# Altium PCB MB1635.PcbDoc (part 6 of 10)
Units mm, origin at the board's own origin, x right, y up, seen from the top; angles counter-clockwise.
Board outline 127 x 97 mm, 6 copper layers (Top Layer, Signal Layer 1, Signal Layer 2, Signal Layer 3, Signal Layer 4, Bottom Layer), stack 1.557 mm thick; 593 components, 478 nets, 2435 pads, 1743 vias.
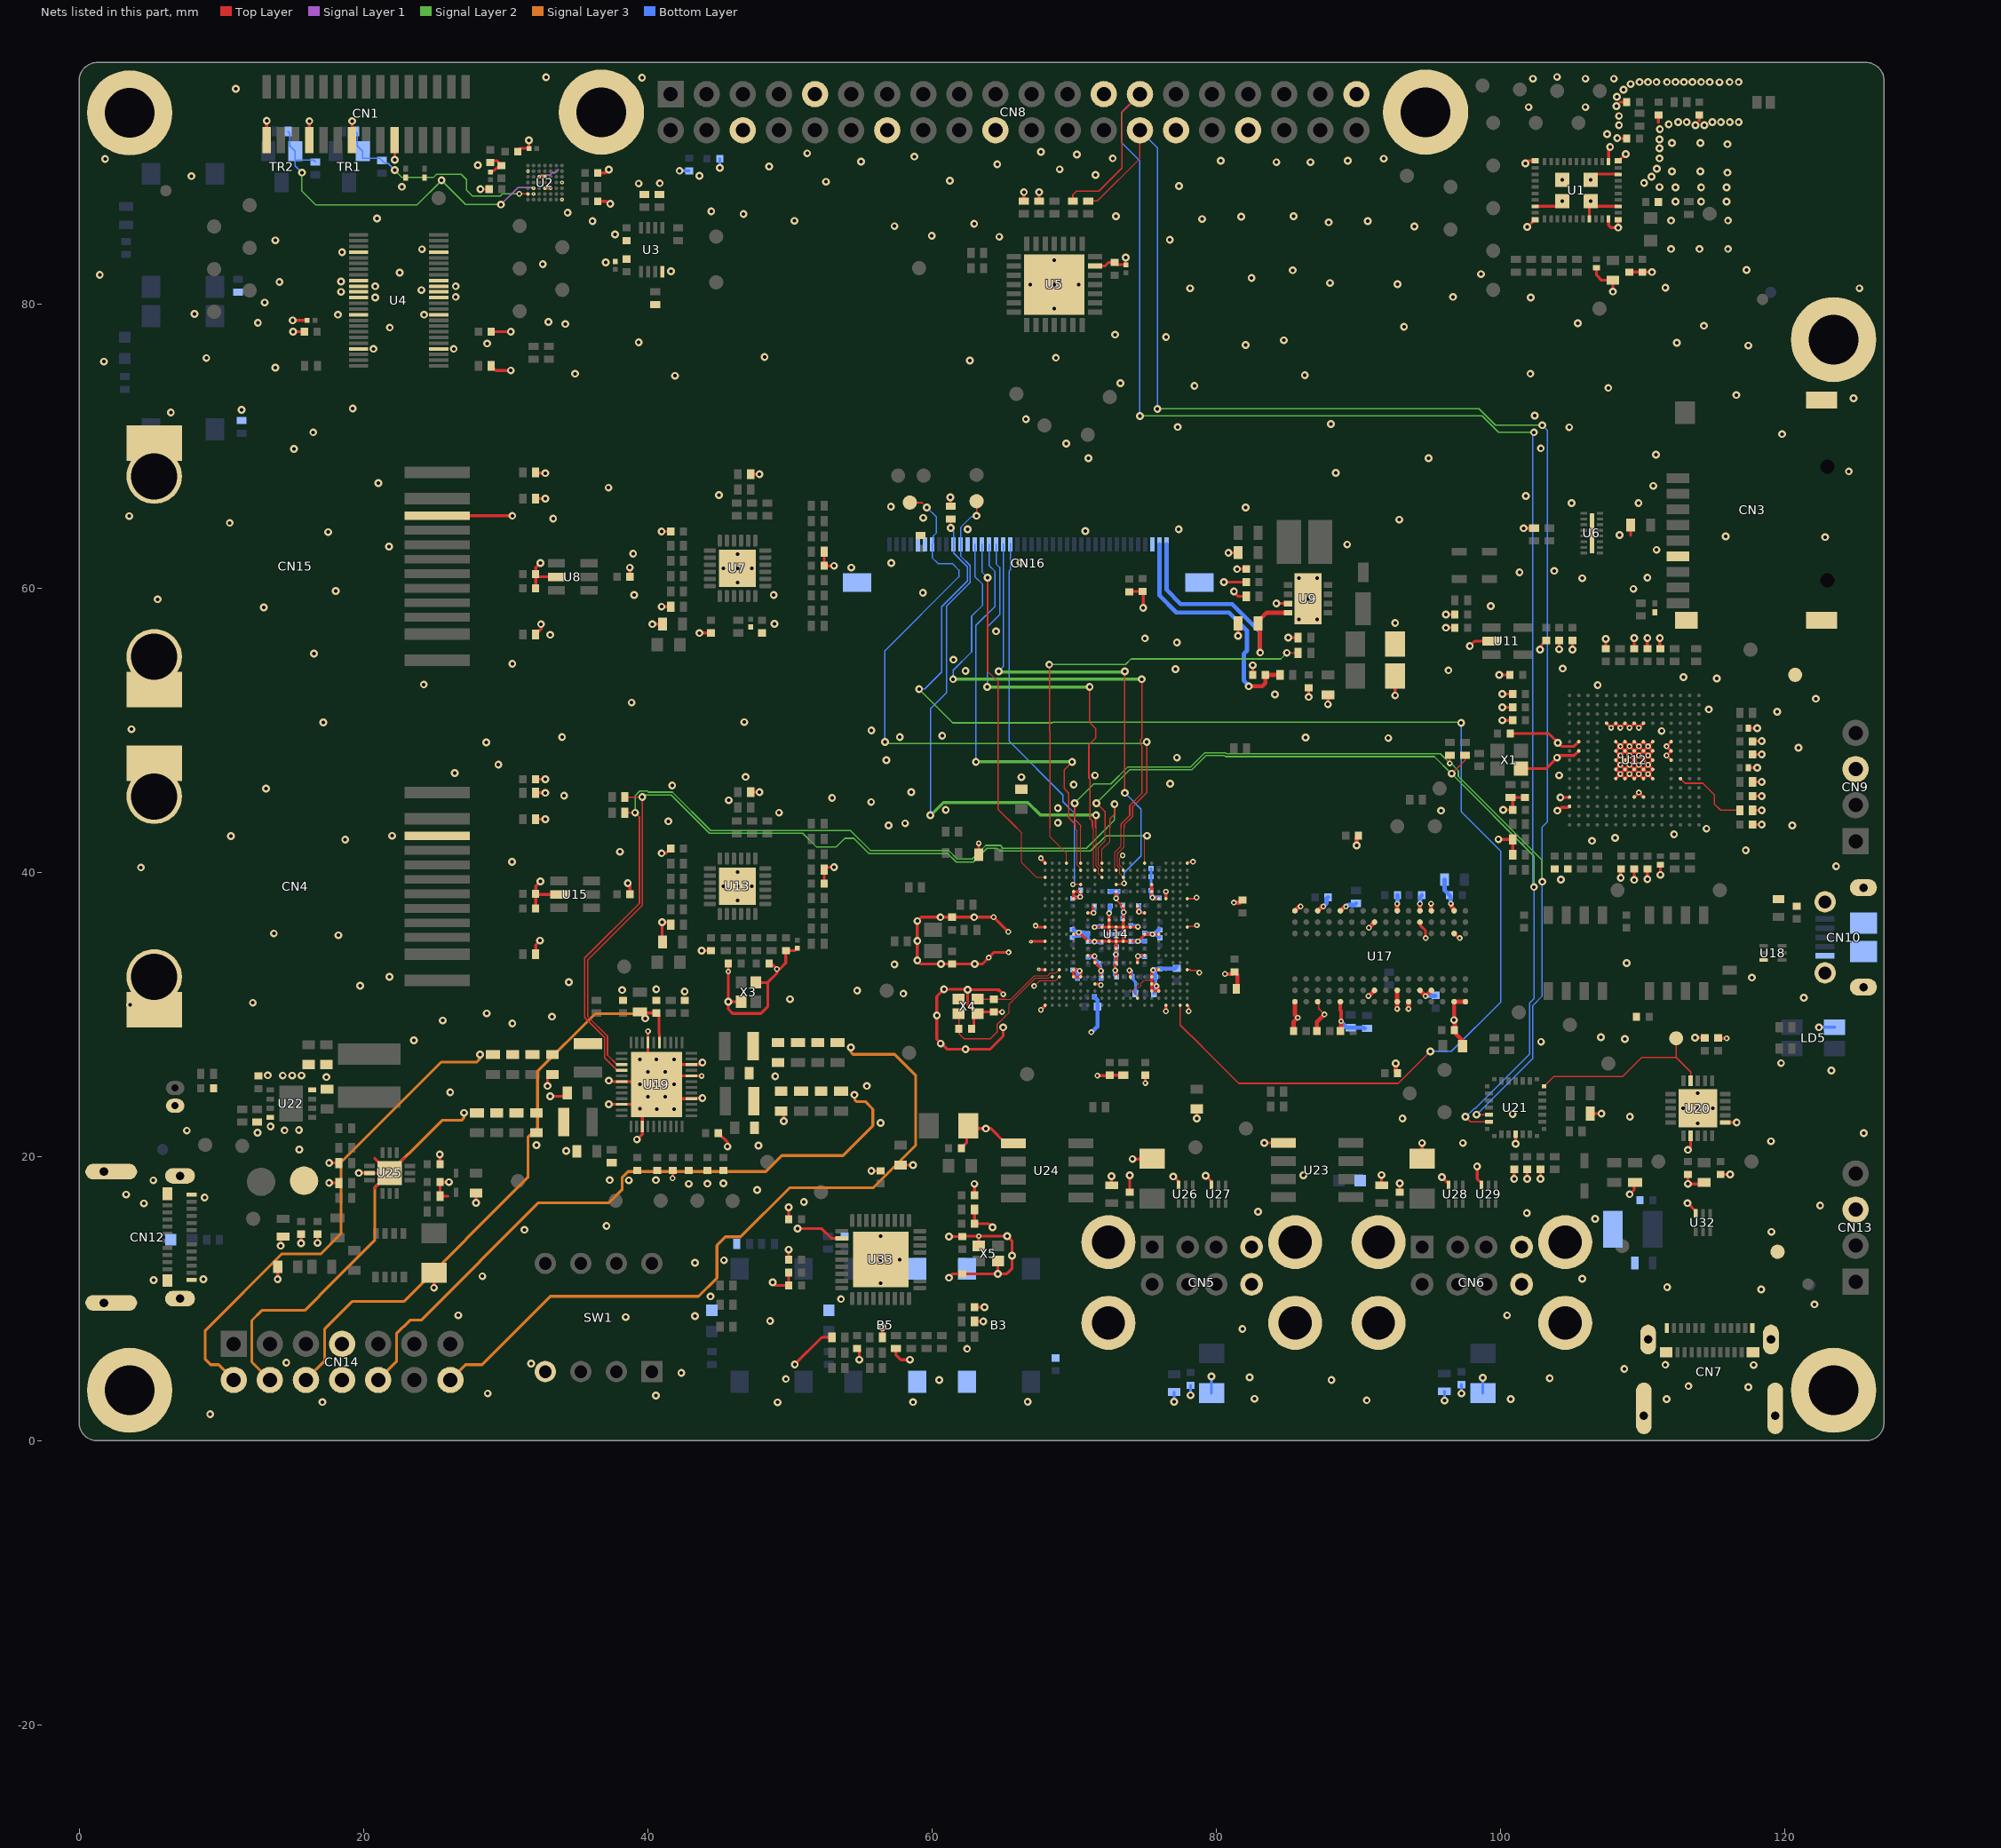
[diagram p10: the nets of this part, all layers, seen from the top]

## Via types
v1: diameter 0.55, hole 0.25, Top Layer to Bottom Layer, 1438 vias
v2: diameter 0.4, hole 0.2, Top Layer to Bottom Layer, 276 vias
v3: diameter 0.26, hole 0.1, Top Layer to Signal Layer 1, tented both sides, 29 vias

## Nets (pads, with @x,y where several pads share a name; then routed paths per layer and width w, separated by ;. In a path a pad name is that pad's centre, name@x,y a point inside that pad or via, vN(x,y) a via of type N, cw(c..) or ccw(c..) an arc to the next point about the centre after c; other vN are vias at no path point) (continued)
GND: B3.1 B3.2 B5.3 B5.4 C1.1 C2.1 C3.1 C4.1 C5.1 C6.1 C7.2 C8.1 C9.1 C10.1 C11.1 C12.1 C13.1 C14.1 C15.1 C16.1 C17.1 C18.1 C19.1 C20.1 C21.1 C22.1 C23.1 C24.1 C25.1 C26.1 C27.1 C28.1 C29.2 C30.1 C31.1 C32.1 C33.2 C34.1 C35.1 C36.2 C37.1 C38.1 C39.2 C40.1 C41.1 C42.1 C43.1 C44.1 C45.1 C46.1 C47.1 C48.1 C49.1 C50.2 C51.1 C52.1 C53.1 C54.1 C55.1 C56.1 C57.1 C58.1 C59.1 C60.1 C61.1 C62.1 C63.1 C64.1 C65.1 C66.1 C67.1 C68.1 C69.1 C70.1 C71.1 C72.1 C73.1 C74.1 C75.1 C76.1 C77.1 C78.1 C79.1 C80.1 C81.2 C82.1 C83.1 C84.1 C85.1 C88.2 C89.1 C90.1 C91.2 C92.1 C93.2 C94.1 C95.1 C96.1 C98.1 C99.2 C100.1 C101.1 C102.1 C103.2 C104.1 C105.1 C106.1 C107.2 C108.1 C109.1 C110.1 C112.1 C113.1 C114.1 C116.1 C117.1 C118.2 C119.1 C120.1 C121.1 C122.1 C123.1 C124.1 C125.1 C126.1 C129.1 C130.1 C131.1 C132.1 C133.1 C134.1 C135.1 C136.1 C137.1 C138.1 C139.1 C140.1 C141.1 C142.1 C143.1 C144.1 C145.1 C146.1 C147.1 C148.1 C149.1 C150.1 C151.1 C152.1 C153.1 C154.1 C155.2 C156.1 C157.1 C158.1 C159.1 C160.2 C161.1 C162.2 C163.1 C164.1 C165.1 C166.1 C168.1 C169.1 C170.1 C171.1 C172.1 C173.1 C174.1 C175.1 C176.1 C177.2 C178.1 C179.1 C180.2 C181.1 C182.1 C183.1 C184.1 C185.2 C186.1 C187.1 C188.1 C189.1 C190.1 C191.2 C192.1 C193.1 C194.1 C195.2 C196.1 C197.1 C198.1 C199.1 C200.1 C201.1 C202.1 C203.2 C204.2 C205.1 C206.1 C207.2 C208.1 C209.1 C210.2 C211.1 C212.1 C213.1 C214.2 C215.2 C216.2 C217.2 C218.1 C219.2 C220.1 C221.1 C222.1 C223.1 C224.1 C225.1 C226.1 C227.1 C228.1 C229.1 CN1.1 CN1.4 CN1.7 CN1.10 CN3.6 CN3.10 CN3.11 CN3.12 CN4.10 CN4.13 CN4.14 CN5.B4 CN5.CH1 CN5.CH2 CN5.CH3 CN5.CH4 CN5.T4 CN6.B4 CN6.CH1 CN6.CH2 CN6.CH3 CN6.CH4 CN6.T4 CN7.A1 CN7.A12 CN7.B1 CN7.B12 CN7.SH1 CN7.SH2 CN7.SH3 CN7.SH4 CN8.6 CN8.9 CN8.14 CN8.20 CN8.25 CN8.30 CN8.34 CN8.39 CN9.3 CN10.5 CN10.6 CN10.7 CN10.8 CN10.9 CN10.10 CN10.11 CN11.2 CN12.A1 CN12.A12 CN12.B1 CN12.B12 CN12.SH1 CN12.SH2 CN12.SH3 CN12.SH4 CN13.3 CN14.7 CN14.8 CN15.10 CN15.13 CN15.14 CN16.3 CN16.29 CN16.35 CN16.36 CN16.MT1 CN16.MT2 LD1.2 LD2.2 LD5.4 LD6.2 LD7.2 pad.1 R3.2 R4.2 R7.1 R8.1 R13.1 R23.2 R24.1 R25.2 R27.1 R33.1 R38.2 R44.1 R47.2 R49.1 R52.1 R53.1 R58.2 R59.1 R66.1 R68.2 R69.2 R70.1 R74.1 R76.1 R84.1 R87.1 R93.2 R101.2 R110.1 R112.1 R128.2 R134.1 R136.1 R140.1 R143.1 R145.1 R146.1 R147.1 R148.1 R156.1 R158.1 R159.1 R160.1 R173.2 R175.2 R176.1 R178.1 R179.1 R182.2 SW1.4 TP39.1 TP75.1 TP76.1 U1.1 U1.12 U1.19 U1.21 U1.29 U1.32 U1.33 U1.35 U1.40 U1.42 U1.43 U1.44 U1.45 U1.46 U2.A4 U2.A7 U2.C5 U2.D3 U2.D5 U2.E3 U2.F6 U2.G2 U3.4 U4.4 U4.9 U4.10 U4.11 U4.12 U4.15 U4.21 U4.28 U4.34 U4.37 U4.38 U4.39 U4.40 U4.45 U5.6 U5.29 U6.EP U7.EP U8.2 U9.3 U9.9 U10.2 U11.2 U12.D5 U12.D6 U12.D7 U12.D8 U12.D9 U12.F2 U12.F6 U12.F7 U12.F8 U12.F9 U12.F10 U12.F12 U12.G2 U12.G6 U12.G7 U12.G8 U12.G9 U12.G10 U12.G12 U12.H6 U12.H7 U12.H8 U12.H9 U12.H10 U12.H12 U12.J6 U12.J7 U12.J8 U12.J9 U12.J10 U12.K6 U12.K7 U12.K8 U12.K9 U12.K10 U12.M1 U12.M8 U12.M9 U12.N1 U13.EP U14.A1 U14.A21 U14.AA1 U14.AA18 U14.AA21 U14.B12 U14.D16 U14.E5 U14.E6 U14.E11 U14.E16 U14.F5 U14.F17 U14.F18 U14.F21 U14.G8 U14.G12 U14.G14 U14.H7 U14.H15 U14.J10 U14.J12 U14.K1 U14.K9 U14.K10 U14.K11 U14.K12 U14.K13 U14.K21 U14.L5 U14.L10 U14.L12 U14.L15 U14.L17 U14.M1 U14.M7 U14.M9 U14.M10 U14.M11 U14.M12 U14.M13 U14.N11 U14.P7 U14.P15 U14.R8 U14.R11 U14.R14 U14.T1 U14.T5 U14.T17 U14.T21 U14.U3 U14.U5 U14.U6 U14.U9 U14.U11 U14.U13 U14.U16 U14.V8 U14.V16 U14.W16 U14.W17 U14.Y14 U15.2 U16.2 U17.A9 U17.B1 U17.B3 U17.B9 U17.D1 U17.D8 U17.E1 U17.E2 U17.E8 U17.F9 U17.G1 U17.G8 U17.G9 U17.J2 U17.J8 U17.M1 U17.M9 U17.P1 U17.P9 U17.T1 U17.T9 U18.3 U19.6 U19.10 U19.15 U19.26 U19.30 U19.32 U19.41 U19.ep U20.12 U20.16 U20.21 U21.4 U22.4 U22.8 U23.1 U24.1 U25.2 U25.13 U26.3 U27.3 U28.3 U29.3 U30.2 U31.2 U32.3 U33.11 U33.37 U34.2 U36.2 U37.2 U38.2 U39.2 U40.2 U41.2 X1.2 X3.2 X3.4 X4.2 X4.4 X5.2 X5.4 | length 429.6
  Top Layer w0.075: v2(67.2,32) 67.597,32.397 68.722,32.397 U14.U3@68.975,32.65 ; v2(73.425,41.2) 73.228,41.003 73.228,40.522 73.452,40.298 73.452,40.173 U14.B12@73.469,40.156 ; U14.Y14@74.475,31.15 74.464,31.161 74.464,31.312 74.228,31.548 74.228,31.803 74.328,31.903 74.576,31.903 74.722,32.049 74.722,32.189 74.933,32.4 75.475,32.4
  Top Layer w0.09: U14.T21@77.974,33.15 78.156,33.15 78.216,33.09 78.617,33.09 78.757,32.95 v2(78.825,32.95) ; C94.1@81.15,32.85 C94.1@81.3,33 ; U17.P9@87.15,30.9 87.22,30.83 87.22,30.405 v2(87.625,30) ; v2(90.725,31.3) v2@90.75,31.3
  Top Layer w0.1: U14.K21@77.974,36.15 77.98,36.145 78.035,36.2 78.491,36.2 78.566,36.275 v2(78.65,36.275)
  Top Layer w0.12: U17.T1@85.47,37.37 U17.T1@85.545,37.295 ; U17.M1@88.745,37.295 U17.M1@88.745,37.395 ; v2@92.745,30.305 v2(92.745,30.395) ; U17.E8@94.345,31.695 U17.E8@94.365,31.695
  Top Layer w0.15: v2(72.975,38.175) 72.975,38.074 U14.G12@73.393,37.656 ; U14.AA21@77.974,30.65 78.075,30.55 v2(78.075,30.225) ; U14.F21@77.975,38.15 78.482,38.15 78.557,38.225 v2(78.625,38.225)
  Top Layer w0.175: v2@74.475,33.989 v2@74.636,34.15 ; U14.A21@77.953,40.652 77.992,40.652 78.068,40.729 78.354,40.729 v2(78.375,40.75)
  Top Layer w0.2: CN1.1@13.2,91.525 v1(13.2,92.9) ; U22.4@13.45,22.75 U22.4@13.46,22.74 ; v1@13.46,22.256 13.475,22.241 v1(13.475,22.125) ; v1(13.975,11.375) C166.1@13.975,12.25 ; v1(14.175,13.725) 14.175,14.184 14.17,14.189 U34.2@14.345,14.364 ; v1(15.025,78.85) C24.1@16.05,78.85 ; v1(15.05,78.05) C25.1@15.85,78.05 ; C161.1@15.62,14.539 15.625,14.534 v1(15.625,13.9) ; CN1.4@16.2,91.5 CN1.4@16.2,91.525 v1(16.2,92.875) ; v1(16.77,13.918) C160.2@16.77,14.493 ; v1(17.6,18.15) 18.259,18.15 R147.1@18.27,18.139 ; v1(17.6,19.55) 18.259,19.55 R145.1@18.27,19.539 ; CN1.7@19.2,91.5 CN1.7@19.2,91.525 v1(19.2,92.875) ; v1(19.675,18.85) 20.409,18.85 U25.2@20.42,18.839 U25.13@21.841,18.839 ; 20.795,17.792 U25.13@21.841,18.839 ; 20.795,19.889 U25.13@21.843,18.841 ; U25.13@21.845,18.842 U25.13@21.843,18.841 ; v1(22.2,90.15) CN1.10@22.2,91.5 ; 22.891,19.889 U25.13@21.841,18.839 ; v1(24.97,10.764) C162.2@24.97,11.814 ; CN15.10@25.2,65.1 v1(30.475,65.1) ; v1(25.375,20.15) 25.375,19.484 C151.1@25.395,19.464 ; C156.1@25.395,18.214 25.409,18.2 v1(26.025,18.2) ; C156.1@25.4,18.175 25.395,18.175 R148.1@25.395,17.214 25.945,17.214 ; C155.2@27.92,17.439 27.925,17.434 v1(27.925,16.75) ; v1(28.225,88.075) C12.1@28.85,88.075 ; C117.1@28.925,89.95 29.062,90.087 29.388,90.087 29.7,89.775 29.52,89.595 29.423,89.595 29.403,89.575 29.384,89.575 29.179,89.37 29.025,89.37 C10.1@28.95,89.295 ; R23.2@29,75.65 29.325,75.325 v1(30.375,75.325) ; C26.1@29,78.05 29.004,78.054 v1(30.376,78.054) ; C6.1@30.875,90.825 31,90.95 C5.1@31.65,90.95 v1(31.65,91.525) ; R110.1@32.125,34.25 32.125,34.9 v1(32.425,35.2) ; C85.1@32.125,37.475 32.125,38.4 C80.1@32.175,38.45 ; R76.1@32.125,43.75 v1(32.8,43.75) ; R70.1@32.125,45.6 v1(32.8,45.6) ; C229.1@32.125,46.55 v1(32.8,46.55) ; R52.1@32.125,56.75 32.5,57.125 v1(32.5,57.475) ; C35.1@32.125,60 C32.1@32.125,61 ; R27.1@32.125,66.3 v1(32.8,66.3) ; R24.1@32.125,68.15 32.175,68.1 v1(32.8,68.1) ; v3(32.375,88.95) U2.D3@32.775,88.95 ; v1(32.45,39.375) 32.125,39.05 C80.1@32.125,38.5 C80.1@32.175,38.45 ; v1(32.45,61.775) 32.125,61.45 C32.1@32.125,61 ; U2.D5@32.775,88.15 v3(33.175,88.15) ; v1(32.95,24.975) 32.95,25.725 33,25.775 C116.1@33.3,25.775 ; v1(33.15,24.25) 34.125,24.25 C125.1@34.35,24.475 ; U8.2@33.575,60.8 32.325,60.8 C32.1@32.125,61 ; U15.2@33.75,38.45 C80.1@32.175,38.45 ; C14.1@36.5,87.225 37.105,87.225 37.28,87.05 v1(37.375,87.05) ; C11.1@36.5,89.225 37.05,89.225 v1(37.275,89.45) ; v1(37.275,23.675) U19.10@38.175,23.675 39.225,23.675 U19.ep@39.625,24.075 ; v1(37.277,25.351) 37.371,25.351 37.448,25.275 U19.6@38.175,25.275 U19.ep@40.425,25.275 ; v1(38.6,39.25) 38.75,39.1 C81.2@38.75,38.45 ; C33.2@38.75,60.8 v1(38.75,61.45) ; v1(39.25,21.2) 39.625,21.575 U19.15@39.625,22.125 U19.ep@39.625,24.075 ; v2(40.025,28.825) U19.41@40.025,28.025 40.025,25.675 U19.ep@40.425,25.275 ; v1(40.325,57.475) C39.2@41.05,57.475 ; v1(40.975,41.35) 41.3,41.35 C71.1@41.625,41.675 ; v1(40.975,58.7) R47.2@41.625,58.7 ; v1(40.975,64) C28.1@41.625,64 ; C91.2@41.05,35.1 41.125,35.175 41.025,35.275 v1(41.025,36.5) 41.45,36.5 R101.2@41.625,36.325 ; v2(41.752,18.476) 41.763,18.487 41.763,19.013 C143.1@41.775,19.025 ; v1(43.65,56.85) C37.1@44.45,56.85 ; v2(43.8,25.675) U19.30@43.075,25.675 42.775,25.675 42.774,25.674 U19.ep@41.224,25.674 ; v1(43.8,34.5) C89.1@44.45,34.5 ; v1(43.852,24.126) 43.829,24.103 43.462,24.103 43.434,24.075 U19.26@43.075,24.075 41.625,24.075 v1(40.625,25.075) ; v1(43.852,26.626) 43.757,26.626 43.606,26.475 U19.32@43.075,26.475 42.025,26.475 U19.ep@41.224,25.674 ; C132.1@44.975,21.65 45.625,21 v1(45.625,20.7) ; C95.1@45.675,33.6 v2(45.675,33.025) v1(45.675,30.9) ; X3.4@46.575,30.9 v1(45.675,30.9) ; R69.2@47.25,45.65 v1(47.875,45.65) ; R25.2@47.25,68.025 v1(47.875,68.025) ; X3.2@47.625,32.25 48.45,32.25 ; C96.1@48.55,33.6 48.7,33.6 v2(49.1,33.2) ; v1(48.8,11.15) 49.025,10.925 C168.1@49.925,10.925 C165.1@49.925,11.85 ; C126.1@49.4,23.2 49.577,23.023 v1(49.577,22.501) ; C163.1@49.925,12.75 v1(49.925,13.45) ; C157.1@49.925,15.6 v1(49.925,16.425) ; v1(50.35,5.375) 52.25,7.275 R158.1@52.975,7.275 ; C92.1@50.525,34.675 50.35,34.5 C90.1@49.725,34.5 49.725,33.625 49.3,33.2 v2(49.1,33.2) ; v1(50.55,14.925) 52.25,14.925 52.925,14.25 U33.11@53.65,14.25 ; C79.1@52.425,39.2 R93.2@52.425,40.2 52.6,40.375 v1(53.125,40.375) ; R38.2@52.425,62.575 C30.1@52.425,61.575 v1(53.125,61.575) ; C170.1@54.75,6.5 54.9,6.35 v1(54.9,5.7) ; v1(55.75,19) C150.1@56.4,19 ; R159.1@56.525,7.275 v1(56.525,8) ; R160.1@57.475,6.5 57.475,6.05 57.825,5.7 v1(58.45,5.7) ; C133.1@57.8,19.4 v1(58.675,19.4) ; v1(60.625,27.95) 60.7,27.95 61.1,27.55 v1(62.375,27.55) 64.081,27.55 65.025,28.494 v1(65.025,29.1) ; v1@60.646,27.971 60.35,28.268 v1(60.35,29.925) 60.35,30.02 60.35,31.275 v1(60.85,31.775) 62.525,31.775 62.528,31.772 v1(62.528,31.752) ; v1(61.2,11.475) 61.475,11.75 C164.1@62.15,11.75 v1(64.65,11.75) ; v1(61.2,14.375) C159.1@62.15,14.375 62.175,14.4 v2(63.3,14.4) ; v1(61.3,66.4) 61.3,65.85 61.35,65.8 R59.1@61.325,65.775 ; C135.1@62.075,20.6 62.45,20.975 62.45,22.05 C130.1@62.575,22.175 62.775,21.975 v1(63.8,21.975) 64.15,21.975 65.195,20.93 U24.1@65.725,20.93 ; C103.2@62.8,29 62.95,29.15 62.95,29.825 X4.2@63.2,30.075 ; R156.1@63,8.4 v1(63.625,8.4) ; C169.1@63,9.4 v1(63.7,9.4) ; R146.1@63,16.275 C158.1@63,15.275 64.025,15.275 v1(64.275,15.025) ; C154.1@63,17.275 v1(63,18.075) ; X5.2@63.3,13.7 v2(63.3,14.4) ; C72.1@63.3,41.25 v2@63.3,41.975 ; X5.4@64.65,12.65 v1(64.65,11.75) ; v2(64.95,30.175) C98.1@64.375,30.175 63.3,30.175 X4.2@63.2,30.075 ; v2(65.025,31.425) 64.7,31.75 64.65,31.7 64.598,31.752 v1(62.528,31.752) ; v2(65.375,35.825) v2(64.35,36.85) v1(62.975,36.85) C88.2@61.425,36.85 v1(60.6,36.85) 59.25,36.85 v1(58.975,36.575) v1(58.975,35.188) v1(58.975,33.8) 59.225,33.55 v1(60.65,33.55) C93.2@61.425,33.55 v1(63.025,33.55) 63.55,33.55 v2(64,34) 64.375,34.375 v2(65.4,34.375) ; R7.1@66.475,87.25 v1(66.475,87.875) ; v3@66.975,35.15 U14.M1@67.975,35.15 ; v2(67.3,36.25) 67.4,36.15 U14.K1@67.975,36.15 ; R8.1@67.55,87.25 v1(67.55,87.875) ; v3@67.558,33.15 U14.T1@67.975,33.15 ; U14.L5@69.975,35.65 69.981,35.656 70.177,35.656 70.296,35.775 v2(70.35,35.775) 70.65,35.475 70.666,35.475 70.9,35.241 70.9,35.233 70.975,35.158 U14.M7@70.975,35.15 71.425,35.15 v2(71.45,35.125) 71.475,35.15 U14.M10@72.475,35.15 ; v2@70.425,38.275 70.431,38.269 v2@70.436,38.269 ; U14.E6@70.475,38.65 U14.E6@70.475,38.644 ; U14.P7@70.975,34.15 71.296,34.15 71.346,34.1 v2@71.438,34.1 ; U14.H7@70.975,37.15 70.977,37.152 71.373,37.152 v2(71.375,37.15) 71.375,37.204 71.329,37.251 71.329,37.504 U14.G8@71.475,37.65 ; v2@71.419,34.081 v2@71.438,34.1 ; v2(71.45,34.1) v2@71.438,34.1 ; v2@71.451,36.15 U14.K10@72.475,36.15 ; U14.V8@71.475,32.15 71.825,32.15 v2@71.9,32.075 ; v2@71.475,33.971 U14.R8@71.475,33.65 71.862,33.263 71.862,33.113 v2(71.9,33.075) 71.9,32.733 71.975,32.658 U14.U9@71.975,32.65 ; U5.6@71.475,82.675 72.175,82.675 72.425,82.925 C22.1@72.85,82.925 73,82.775 73.625,82.775 C23.1@73.65,82.75 v1(73.65,83.275) ; v2(71.65,25.7) 72.5,25.7 C118.2@72.525,25.725 R128.2@73.475,25.725 ; U14.L10@72.475,35.617 U14.M10@72.475,35.15 U14.M11@72.975,35.15 ; U14.L10@72.475,35.683 U14.K10@72.475,36.15 ; v2(72.475,37.125) U14.K10@72.475,36.15 ; U30.2@72.65,17.975 v1(72.65,18.625) ; v2(72.9,33.1) 72.9,33.567 72.975,33.642 v2@72.975,34.225 ; v2(72.95,34.225) v2@72.975,34.225 ; U14.U11@72.975,32.65 v2@72.975,33.1 ; v2(72.975,38.175) U14.E11@72.975,38.65 ; U14.G12@73.393,37.656 73.469,37.656 U14.G12@73.475,37.65 v2@73.475,37.199 ; v2@73.476,37.2 v2(73.5,37.2) 73.5,37.176 73.48,37.156 73.48,36.655 73.475,36.65 U14.K12@73.475,36.15 ; v2(73.9,33.1) 73.975,33.1 U14.U13@73.975,32.65 ; C50.2@73.905,59.775 74.83,59.775 74.875,59.73 v1(74.875,58.625) ; C152.1@73.925,17.5 v1(73.925,18.675) ; v1(74.125,19.825) C136.1@75.323,19.825 ; U14.R14@74.475,33.65 v2@74.475,33.989 ; U14.G14@74.475,37.65 74.481,37.644 U14.G14@74.481,37.623 ; U14.G14@74.481,37.623 74.481,37.373 74.575,37.279 v2(74.575,37.225) 74.604,37.225 74.654,37.275 74.773,37.156 74.969,37.156 U14.H15@74.975,37.15 ; v2(74.5,36.175) 74.475,36.15 U14.K12@73.475,36.15 ; v2@74.636,34.15 U14.P15@74.975,34.15 ; v2(75.025,25.175) C119.1@75.025,25.725 ; C136.1@75.324,19.826 75.4,19.75 C136.1@75.5,19.85 ; U14.V16@75.45,32.125 75.474,32.101 U14.W16@75.474,31.65 ; U14.V16@75.474,32.15 75.48,32.144 75.686,32.144 v2@75.804,32.027 ; U14.W16@75.474,31.65 75.974,31.65 75.969,31.656 75.969,31.704 75.912,31.761 75.912,31.918 v2@75.804,32.027 ; U14.V16@75.475,32.175 75.475,32.4 75.475,32.971 75.575,33.071 v2(75.575,33.125) ; U14.D16@75.475,39.15 75.475,38.329 75.525,38.279 v2(75.525,38.225) 75.579,38.225 75.654,38.15 U14.F17@75.975,38.15 ; v2@75.538,33.125 75.519,33.144 75.969,33.144 U14.T17@75.975,33.15 ; v2(75.804,32.002) v2@75.804,32.027 ; U14.L17@75.974,35.65 v2(75.525,35.65) U14.L15@74.975,35.65 74.969,35.644 74.969,35.604 74.515,35.15 v2(74.5,35.15) U14.M12@73.475,35.15 ; v2(76.475,30.225) U14.AA18@76.475,30.65 ; U14.F18@76.475,38.15 v2(76.475,38.65) ; v1(76.979,18.601) 77.024,18.601 77.35,18.275 U26.3@77.35,18 ; v1(78.65,22.675) C124.1@78.65,23.35 ; v1(79.275,18.65) 79.675,18.25 U27.3@79.675,18 ; v1(80.55,60.425) C34.1@82.125,60.425 ; v1(80.875,62.5) C29.2@81.55,62.5 ; v1(81.254,59.778) 81.254,59.746 81.575,59.425 R44.1@82.125,59.425 ; v1(81.475,61.35) C31.1@82.125,61.35 ; v1(81.55,56.65) R49.1@81.55,57.525 ; C54.1@82.575,53.9 v1(82.575,54.575) ; v1(83.395,20.955) U23.1@84.725,20.955 ; v1(84.25,58.925) U9.3@85.075,58.925 ; v1(85.075,56.525) R53.1@85.775,56.525 ; v1(86.525,52.35) C56.1@86.525,53 ; v1(87.875,51.825) C52.1@87.875,52.5 ; U31.2@91.65,17.975 v1@91.65,18.65 ; v1(92.6,52.45) C51.1@92.6,53.825 ; C153.1@92.925,17.5 v1(92.925,18.125) ; U17.E2@94.35,36.5 94.388,36.461 94.388,36.254 94.744,35.899 94.744,35.381 v2(94.75,35.375) ; C137.1@94.5,19.85 v1(94.5,20.95) ; v1(95.9,18.55) 96.35,18.1 U28.3@96.35,18 ; v1(96.175,57.225) C41.1@96.8,57.225 ; v1(96.175,58.15) C36.2@96.8,58.15 ; U17.B3@96.78,35.67 97.075,35.375 v2(97.15,35.375) ; v1(97.85,55.925) 98.2,56.275 U11.2@99.375,56.275 ; v1(98.375,19.3) 98.375,18.425 98.675,18.125 U29.3@98.675,18 ; v1(99.875,42.325) R84.1@100.875,42.325 R87.1@100.875,41.25 ; v1(99.925,53.9) C55.1@100.675,53.9 ; v1(100.15,50.7) C59.1@100.875,50.7 ; v1(100.15,51.625) C58.1@100.875,51.625 ; v1(100.15,52.55) C57.1@100.875,52.55 ; v1(100.2,44.4) C68.1@100.875,44.4 100.875,45.125 R68.2@100.725,45.275 C65.1@101.725,45.275 ; C61.1@100.7,49.775 103.4,49.775 v1(104.05,49.125) 104.3,48.875 105.2,48.875 U12.F2@105.525,49.2 ; v1(100.975,18.425) C138.1@100.975,19.1 ; v1(101.075,20.9) U21.4@101.075,21.575 ; X1.2@101.45,47.3 103.225,47.3 104.15,48.225 105.2,48.225 U12.G2@105.525,48.55 ; v1@101.7,64.225 R33.1@102.375,64.225 ; v1(101.775,89.9) 101.962,90.087 U1.12@102.45,90.087 ; v1(101.9,18.425) C139.1@101.9,19.1 ; v1(101.9,85.425) 101.925,85.425 102.413,85.913 U1.21@102.45,85.913 ; U1.19@102.45,86.875 104,86.875 v1(104.375,87.25) ; v1(102.8,55.675) 102.8,55.9 C42.1@103.225,56.325 ; v1(102.825,18.425) C140.1@102.825,19.1 ; v1(104.025,44.35) 104.092,44.35 104.317,44.575 104.786,44.575 104.861,44.65 U12.N1@104.875,44.65 ; v1(104.15,55.7) C43.1@104.15,56.325 ; v1(104.225,45.275) 104.85,45.275 U12.M1@104.875,45.3 ; v1(105.075,55.675) C44.1@105.075,56.325 ; U1.29@106.275,85.975 106.275,87.15 v1(106.375,87.25) 106.75,86.875 U1.35@108.3,86.875 ; R134.1@106.325,23.025 v1(107.125,23.025) ; v1(106.375,88.75) 106.775,89.15 107.378,89.15 107.772,89.15 108.275,89.15 U1.40@108.3,89.125 ; C18.1@106.775,82.55 106.775,82.025 107.125,81.675 C19.1@107.925,81.675 107.925,81.175 ; C46.1@107.425,55.75 v1(107.425,56.425) ; U12.D5@107.475,50.5 v2(107.8,50.175) U12.D6@108.125,50.5 v2(108.45,50.175) U12.D7@108.775,50.5 v2(109.1,50.175) U12.D8@109.425,50.5 v2(109.75,50.175) U12.D9@110.075,50.5 ; U1.32@107.625,85.975 107.625,85.525 107.775,85.375 v1(108.3,85.375) U1.33@108.3,85.913 ; U1.1@107.625,90.025 107.625,90.95 v1(107.725,91.05) ; U12.K6@108.125,46.6 v2(108.45,46.925) ; U12.F6@108.125,49.2 v2(108.45,48.875) ; U1.42@108.3,90.087 108.362,90.087 v1(108.825,90.55) ; 108.425,94.2 C1.1@108.9,94.2 ; v1(108.475,39.625) 108.475,40.225 C76.1@108.5,40.25 ; v1@108.475,91.65 C4.1@108.9,91.65 ; C20.1@109.075,82.25 C21.1@110,82.25 v1(110.675,82.25) ; v1(109.1,17.35) 109.422,17.672 109.422,18.122 R143.1@109.475,18.175 ; 109.175,63.725 C27.1@109.175,64.45 ; v1(109.425,39.475) C77.1@109.425,40.25 ; U12.M8@109.425,45.3 v2(109.75,45.625) U12.M9@110.075,45.3 ; C47.1@109.425,55.75 v1(109.425,56.5) ; v1(110.35,39.525) C78.1@110.35,40.25 ; C48.1@110.35,55.75 v1(110.35,56.5) ; U12.K10@110.725,46.6 v2(110.4,46.925) ; U12.F10@110.725,49.2 v2(110.4,48.875) ; 111.125,92.775 111.125,93.275 C2.1@111.15,93.3 ; v1(111.225,56.5) 111.225,55.8 C49.1@111.275,55.75 ; v1(111.275,39.825) C73.1@111.275,40.55 ; U12.H12@112.025,47.9 v2(111.7,48.225) U12.G12@112.025,48.55 v2(111.7,48.875) U12.F12@112.025,49.2 ; v1(113.175,16.725) 113.75,16.15 U32.3@113.75,16 ; C147.1@113.2,18.75 v1(113.2,18.075) 114.25,18.075 C149.1@114.35,18.175 ; v1(113.2,20.475) 113.4,20.675 U20.12@113.4,21.475 ; v1(113.7,28.375) 114.375,28.375 C108.1@114.4,28.35 ; 114,92.9 C3.1@114,93.3 ; C109.1@115.325,28.35 115.35,28.325 v2(115.925,28.325) ; C148.1@115.5,18.75 v1(116.175,18.75) ; U20.16@115.825,22.4 v1(116.625,22.4) ; C64.1@117.45,47.375 v1(118.075,47.375) ; C60.1@117.45,50.15 v1(118.075,50.15) ; C69.1@117.75,43.375 v1(118.4,43.375) ; R74.1@117.75,44.375 v1(118.4,44.375) ; C67.1@117.75,45.375 v1(118.4,45.375) ; R66.1@117.75,46.375 v1(118.4,46.375) ; C63.1@117.75,48.3 v1(118.4,48.3) ; C62.1@117.75,49.225 117.775,49.25 v1(118.4,49.25) ; U25.13@21.841,18.839 U25.13@21.845,18.839 U25.13@21.843,18.841 ; U25.13@21.841,18.839 U25.13@21.843,18.841 ; U19.ep@39.625,24.075 v1(40.625,25.075) ; U19.ep@40.425,25.275 v1(40.625,25.075) ; v1(40.625,25.075) U19.ep@41.224,25.674 ; v1(45.675,30.9) 45.675,30.375 45.975,30.075 47.975,30.075 48.45,30.55 48.45,32.25 ; 48.45,32.25 49.1,32.9 v2(49.1,33.2) ; v1(62.528,31.752) 62.528,30.672 63.125,30.075 X4.2@63.2,30.075 ; v2(63.3,14.4) v1(65.3,14.4) 65.65,14.05 v1(65.65,13.025) 65.65,12.125 65.275,11.75 v1(64.65,11.75) ; v2@70.436,38.269 v2(70.436,38.274) 70.436,38.318 70.425,38.329 70.475,38.379 U14.E6@70.475,38.644 ; v2@70.436,38.269 70.342,38.175 70,38.175 U14.F5@69.975,38.15 U14.E5@69.975,38.65 69.981,38.644 U14.E6@70.475,38.644 ; U14.K10@72.475,36.15 U14.K11@72.975,36.15 ; v2@72.975,34.225 U14.M11@72.975,35.15 ; U14.M11@72.975,35.15 U14.M12@73.475,35.15 ; U14.M11@72.975,35.15 v2(72.975,35.65) U14.K11@72.975,36.15 ; U14.K11@72.975,36.15 U14.K12@73.475,36.15 ; U14.M12@73.475,35.15 U14.K12@73.475,36.15 ; v2(108.45,46.925) U12.K7@108.775,46.6 v2(109.1,46.925) ; v2(108.45,46.925) U12.J6@108.125,47.25 v2(108.45,47.575) ; v2(108.45,46.925) U12.J7@108.775,47.25 ; v2(108.45,47.575) U12.H7@108.775,47.9 ; v2(108.45,47.575) U12.H6@108.125,47.9 v2(108.45,48.225) ; v2(108.45,47.575) U12.J7@108.775,47.25 ; v2(108.45,48.225) U12.H7@108.775,47.9 ; v2(108.45,48.225) U12.G6@108.125,48.55 v2(108.45,48.875) ; v2(108.45,48.225) U12.G7@108.775,48.55 ; v2(108.45,48.875) U12.F7@108.775,49.2 v2(109.1,48.875) ; v2(108.45,48.875) U12.G7@108.775,48.55 ; U12.J7@108.775,47.25 v2(109.1,47.575) ; U12.J7@108.775,47.25 v2(109.1,46.925) ; U12.H7@108.775,47.9 v2(109.1,47.575) ; U12.H7@108.775,47.9 v2(109.1,48.225) ; U12.G7@108.775,48.55 v2(109.1,48.225) ; U12.G7@108.775,48.55 v2(109.1,48.875) ; v2(109.1,46.925) U12.K8@109.425,46.6 v2(109.75,46.925) ; v2(109.1,46.925) U12.J8@109.425,47.25 ; v2(109.1,47.575) U12.J8@109.425,47.25 ; v2(109.1,47.575) U12.H8@109.425,47.9 ; v2(109.1,48.225) U12.G8@109.425,48.55 ; v2(109.1,48.225) U12.H8@109.425,47.9 ; v2(109.1,48.875) U12.G8@109.425,48.55 ; v2(109.1,48.875) U12.F8@109.425,49.2 v2(109.75,48.875) ; U12.J8@109.425,47.25 v2(109.75,47.575) ; U12.J8@109.425,47.25 v2(109.75,46.925) ; U12.H8@109.425,47.9 v2(109.75,47.575) ; U12.H8@109.425,47.9 v2(109.75,48.225) ; U12.G8@109.425,48.55 v2(109.75,48.875) ; U12.G8@109.425,48.55 v2(109.75,48.225) ; v2(109.75,46.925) U12.K9@110.075,46.6 v2(110.4,46.925) ; v2(109.75,46.925) U12.J9@110.075,47.25 ; v2(109.75,47.575) U12.J9@110.075,47.25 ; v2(109.75,47.575) U12.H9@110.075,47.9 ; v2(109.75,48.225) U12.H9@110.075,47.9 ; v2(109.75,48.225) U12.G9@110.075,48.55 ; v2(109.75,48.875) U12.G9@110.075,48.55 ; v2(109.75,48.875) U12.F9@110.075,49.2 v2(110.4,48.875) ; U12.J9@110.075,47.25 v2(110.4,46.925) ; U12.J9@110.075,47.25 v2(110.4,47.575) ; U12.H9@110.075,47.9 v2(110.4,47.575) ; U12.H9@110.075,47.9 v2(110.4,48.225) ; U12.G9@110.075,48.55 v2(110.4,48.225) ; U12.G9@110.075,48.55 v2(110.4,48.875) ; v2(110.4,46.925) U12.J10@110.725,47.25 v2(110.4,47.575) ; v2(110.4,47.575) U12.H10@110.725,47.9 v2(110.4,48.225) ; v2(110.4,48.225) U12.G10@110.725,48.55 v2(110.4,48.875) ; U14.U5@69.975,32.65 U14.U6@70.475,32.65 70.475,32.658 70.496,32.679 70.496,32.925 70.4,33.021 v2(70.4,33.075) 70.346,33.075 70.271,33.15 U14.T5@69.975,33.15 U14.U5@69.975,32.65
  Top Layer w0.23: v2(67.675,30.325) 67.975,30.625 U14.AA1@67.975,30.65 ; v2(67.675,41) 67.675,40.973 67.975,40.673 U14.A1@67.975,40.65
  Top Layer w0.25: v2(80.625,32.85) C94.1@81.15,32.85 ; U17.M9@88.75,30.9 88.75,30.3 88.8,30.25 v2(88.8,29.525)
  Top Layer w0.3: v2(81.25,37.875) 81.675,37.875 C82.1@81.85,38.05 ; C94.1@81.3,33 81.5,32.8 81.5,32 R112.1@81.4,31.9 ; C105.1@85.45,28.85 85.45,29.475 v2(85.75,29.775) 85.55,29.975 U17.T9@85.55,30.9 ; U17.T1@85.55,37.3 85.831,37.581 85.931,37.581 v2(85.95,37.6) ; U17.P1@87.15,37.3 87.431,37.581 87.531,37.581 v2(87.55,37.6) ; C106.1@87.2,28.95 C106.1@87.1,28.85 87.1,29.475 v2(87.625,30) ; U17.M1@88.745,37.295 U17.M1@88.75,37.3 89.026,37.576 89.126,37.576 v2(89.145,37.595) ; C107.2@88.75,28.85 88.8,28.9 v2(88.8,29.525) ; v1@89.85,41.975 89.9,42.025 89.9,42.45 C70.1@90.025,42.575 ; v2@90.75,31.3 U17.J8@91.15,31.7 ; v2(90.75,36.1) U17.J2@91.145,36.495 ; v1@92.625,26.55 92.65,26.525 92.65,26 C121.1@92.775,25.875 ; v2(92.745,30.395) U17.G8@92.745,31.695 ; U17.G1@92.745,37.295 v2(92.745,37.795) ; v2(93.545,30.395) U17.F9@93.545,30.895 ; v2@94.32,37.795 94.345,37.77 U17.E1@94.345,37.295 ; U17.E8@94.345,31.695 v2(94.745,31.295) U17.D8@95.145,31.695 ; v2(95.125,37.8) 95.125,37.395 95.131,37.39 95.131,37.309 U17.D1@95.145,37.295 ; v2@96.55,37.8 96.544,37.794 96.544,37.754 96.575,37.723 96.575,37.577 96.75,37.402 U17.B1@96.75,37.3 ; C104.1@96.795,28.865 96.795,29.415 96.645,29.565 96.745,29.665 96.745,30.895 U17.A9@97.545,30.895 ; C104.1@96.795,28.895 96.795,28.72 97.37,28.145 C112.1@97.37,27.82
  Signal Layer 1 w0.1: v3(32.375,88.95) 32.394,88.95 32.514,89.07 33.124,89.07 33.292,89.237 33.488,89.237 33.72,89.47
  Bottom Layer w0.09: v2(92.745,37.795) v2@92.775,37.825
  Bottom Layer w0.1: C194.1@70.975,35.7 C194.1@71,35.675 ; v2@76.47,38.645 v2@76.527,38.702
  Bottom Layer w0.2: v1(42.25,89.375) C7.2@42.925,89.375 ; v1(45.075,89.575) C8.1@45.075,90.225 ; C201.1@71,35.15 C194.1@71,35.675 ; v2(71.45,34.1) 71.45,34.096 71.4,34.046 71.675,33.771 71.675,33.6 71.896,33.379 71.896,33.079 v2(71.9,33.075) ; C212.1@74.1,32.65 74.1,32.525 74.325,32.3 C217.2@74.325,31.475 ; C175.1@75.425,38.725 C173.1@75.425,39.7 C171.1@75.425,40.275 ; C216.2@75.575,31.55 C216.2@75.625,31.5 ; C216.2@75.625,31.475 75.725,31.575 75.725,31.846 75.8,31.921 v2@75.8,31.95 ; C211.1@75.75,32.65 75.75,32.075 v2@75.8,32.025 ; v1(77.05,2.75) U39.2@77.05,3.425 ; v1(78.2,3.2) C227.1@78.2,3.9 ; C225.1@79.675,3.35 v1(79.675,4.525) ; v1(96.075,2.825) 96.075,3.394 U38.2@96.075,3.475 ; v1(97.275,3.325) C226.1@97.275,3.95 ; C224.1@98.775,3.35 v1(98.775,4.425) ; v1(122.425,29.1) LD5.4@123.525,29.1
  Bottom Layer w0.3: C207.2@69.975,33.125 70,33.1 70.373,33.1 70.398,33.075 v2(70.4,33.075) 70.4,33.073 v2@70.425,33.048 ; C191.2@69.975,35.975 70.375,35.575 v2@70.438,35.638 ; C197.1@70,35.475 70.08,35.555 70.43,35.555 70.475,35.6 v2@70.438,35.638 ; C183.1@70,38.2 70.025,38.225 70.348,38.225 70.398,38.275 70.404,38.269 70.436,38.269 v2(70.436,38.274) 70.436,38.291 70.425,38.302 70.45,38.327 70.45,38.625 C174.1@70.475,38.65 ; C215.2@70.25,32.55 70.275,32.575 70.275,32.898 v2@70.425,33.048 ; v2@70.425,33.025 v2@70.425,33.048 ; C194.1@70.975,35.7 70.85,35.575 70.65,35.775 v2@70.375,35.775 ; C205.1@71,34.05 71.025,34.075 71.348,34.075 71.373,34.1 v2(71.45,34.1) ; C201.1@71,35.15 71.013,35.138 71.438,35.138 v2(71.45,35.125) 71.463,35.113 71.888,35.113 C202.1@71.9,35.1 ; v2(71.225,28.75) 71.25,28.75 71.655,29.155 C220.1@71.655,30.545 71.655,31.02 C219.2@71.43,31.245 ; v2(71.375,37.15) 71.375,37.152 71.325,37.202 71.425,37.302 71.425,37.6 C187.1@71.45,37.625 ; v2(71.45,36.149) 71.477,36.149 71.503,36.175 71.9,36.175 C190.1@71.925,36.2 ; C214.2@71.9,32.55 71.925,32.575 71.925,33.023 71.9,33.048 v2(71.9,33.075) ; C196.1@72.475,35.65 v2(72.975,35.65) 73.025,35.7 C195.2@73.45,35.7 ; v2(72.475,37.125) 72.475,37.152 72.525,37.202 72.525,37.6 C186.1@72.55,37.625 ; C177.2@72.55,38.7 72.563,38.688 73.088,38.688 C176.1@73.1,38.675 72.994,38.569 72.994,38.194 v2(72.975,38.175) ; v2(72.9,33.1) 72.9,32.775 C213.1@73,32.675 ; v2(72.95,34.225) v2@72.95,34.15 ; C208.1@72.975,33.7 72.95,33.725 v2@72.95,34.15 ; 73,34.55 72.988,34.538 72.988,34.113 v2@72.95,34.15 ; C189.1@73.45,36.75 73.475,36.775 73.475,37.124 73.5,37.149 v2(73.5,37.2) 73.5,37.201 73.475,37.226 73.475,37.625 C185.2@73.45,37.65 ; v2(73.9,33.1) 73.975,33.1 74.025,33.05 74.025,32.75 C212.1@74.1,32.675 ; C188.1@74,36.25 74.025,36.225 74.348,36.225 74.423,36.15 74.448,36.175 v2@74.475,36.175 ; C200.1@74,35.15 v2@74.475,35.15 ; v2@74.463,36.163 v2@74.475,36.175 ; v2@74.475,35.149 74.488,35.162 74.962,35.162 C199.1@74.975,35.175 ; v2(74.5,34.1) 74.519,34.119 C204.2@74.975,34.119 ; v2(74.5,36.175) v2@74.475,36.175 ; C184.1@74.55,37.675 74.575,37.65 74.575,37.327 74.6,37.302 74.575,37.277 v2(74.575,37.225) ; C193.1@74.975,35.725 75,35.7 75.448,35.7 75.498,35.65 v2(75.525,35.65) ; C175.1@75.425,38.675 75.45,38.65 75.45,38.277 75.475,38.252 75.475,38.225 75.488,38.213 75.963,38.213 C182.1@75.975,38.2 ; v2@75.527,33.125 75.577,33.175 75.975,33.175 C206.1@76.025,33.225 ; v2(75.575,33.125) 75.575,33.098 75.7,32.973 75.7,32.675 C211.1@75.725,32.65 ; C198.1@76,35.45 75.819,35.631 75.544,35.631 v2(75.525,35.65) ; C192.1@76,36 75.669,35.669 75.544,35.669 v2(75.525,35.65) ; C206.1@76.05,33.2 76.075,33.225 77.12,33.225 77.12,33.245 C210.2@77.225,33.35 ; v2(87.55,37.6) 87.55,37.605 87.77,37.825 87.77,38.145 C181.1@87.875,38.25 ; v2(88.8,29.525) 88.8,29.463 89.188,29.075 90.4,29.075 R179.1@90.45,29.025 ; v2(89.145,37.595) 89.172,37.595 89.297,37.72 89.745,37.72 R176.1@89.85,37.825 ; v2@92.775,37.825 C180.2@92.775,38.4 ; v2(94.345,37.795) 94.364,37.814 94.364,38.264 94.475,38.375 C179.1@94.475,38.4 ; v2(94.745,31.295) 94.755,31.305 C218.1@95.425,31.305 ; C172.1@96.075,39.5 96.075,38.75 96.506,38.319 96.506,37.819 v2(96.525,37.8) ; v2@70.375,35.775 v2(70.35,35.775) 70.35,35.725 v2@70.438,35.638 ; v2@70.375,35.775 70.475,35.675 v2@70.438,35.638
  other v1: 9.225,1.875 49.15,2.7 17.125,2.725 58.675,2.725 66.75,2.75 90.6,2.85 100.745,2.933 111.7,2.925 82.7,2.95 40.575,3.175 28.75,3.325 117.45,3.775 113.25,3.85 60.525,4.275 88.125,4.275 49.725,4.35 103.475,4.4 82.352,4.473 42.375,4.775 108.725,5.05 117.825,5.325 111.625,5.35 31.8,5.425 14.575,5.5 62.475,6.475 81.85,7.875 48.625,8.425 38.45,8.7 43.325,8.775 26.675,8.825 100.475,8.825 122.1,9.6 53.6,9.975 44.425,10.163 118.35,10.65 111.75,10.8 56.4,11.1 5.233,11.308 8.75,11.367 105.775,11.4 28.375,11.575 43.325,12.525 45.375,12.7 56.4,12.75 57.75,12.75 56.4,14.4 119.075,14.7 31.325,14.85 37.1,15.125 106.675,15.62 101.875,16.025 82.95,16.125 122.5,16.55 4.55,16.7 51,16.8 8.825,17.125 3.3,17.325 47.7,17.65 42.9,18.075 44.2,18.1 45.325,18.125 5.225,18.325 38.677,18.326 37.327,18.351 40.577,18.351 86.15,18.675 91.65,18.7 34.275,20.4 15.5,20.5 47.802,20.776 32.175,20.8 97.375,20.95 119.05,21.075 125.575,21.65 12.55,21.675 7.575,21.825 14.45,21.85 15.475,21.875 113.9,22.35 56.4,22.375 93.125,22.675 109.125,22.8 100.875,23 40.65,23.35 41.875,23.35 39.45,23.375 112.85,23.4 113.9,23.4 114.95,23.4 40.025,24.225 41.225,24.225 113.9,24.45 26.1,24.525 55.425,24.975 39.45,25.1 41.875,25.1 17.4,25.6 48.975,25.65 14.325,25.7 14.988,25.7 15.65,25.7 13.275,25.725 40.025,25.95 41.225,25.95 123.3,26.05 92.65,26.55 119.75,26.575 39.45,26.825 40.625,26.825 41.875,26.825 102.875,28.075 23.55,28.175 108.775,28.275 107.075,28.4 30.475,29.375 25.575,29.575 96.75,29.605 33.275,29.85 28.676,30.076 3.575,30.675 12.225,30.825 50.025,31.075 121.35,31.175 58,31.475 42.6,31.625 54.75,31.675 38.2,31.725 40.602,31.776 19.775,32.025 34.45,32.275 117.7,32.6 21.825,32.65 57.375,33.525 108.9,33.625 18.25,35.575 13.7,35.7 46.325,38.025 45.325,39.025 46.325,39.025 47.325,39.025 104.275,39.5 46.325,40.025 4.35,40.35 123.625,40.425 30.45,40.75 38.05,41.45 117.275,41.55 89.9,41.9 106.45,42.225 18.722,42.296 108.075,42.425 10.675,42.55 22.025,42.575 112.225,42.675 114.5,43.075 56.95,43.3 120.55,43.3 58.125,43.45 68.875,43.5 41.45,43.6 49.25,44.2 95.825,44.35 60.975,44.4 68.875,44.525 55.725,44.95 45.7,45.075 52.975,45.25 34.125,45.4 58.55,45.65 13.15,45.9 41.725,46.125 69.975,46.175 76.775,46.25 66.3,46.7 46.9,46.725 71.475,46.825 104.15,46.825 26.425,47 29.501,47.577 56.8,47.9 77.25,48.075 104,48.075 120.975,48.775 28.65,49.15 92.125,49.45 86.3,49.5 33.975,49.525 57.75,49.525 60.725,49.625 111.35,49.95 55.75,50 3.675,50.075 17.175,50.55 46.8,50.575 119.475,51.3 114.675,51.475 38.875,51.95 122.2,52.225 84.15,52.525 106.85,53.175 24.25,53.225 115.225,53.65 112.9,53.75 62.375,54.175 96.35,54.225 77.15,54.3 104.4,54.35 30.475,54.675 61.525,54.975 16.525,55.4 77.25,56.175 75,56.475 33.15,56.725 64.525,56.975 48.925,57.5 92.6,57.55 85.825,57.8 87.125,57.8 13,58.65 99.325,58.75 5.525,59.225 86.475,59.25 39.05,59.525 48.875,59.525 59.375,59.675 18.05,59.8 109.375,59.95 46.325,60.4 85.825,60.7 87.125,60.7 105.775,60.7 110.35,60.75 101.35,61.125 103.8,61.225 45.325,61.4 46.325,61.4 47.325,61.4 54.325,61.45 57.15,61.775 66.225,61.8 46.325,62.4 38.975,62.425 111,62.7 21.8,62.925 89.225,63.075 122.85,63.6 115.85,63.65 108.4,63.75 17.525,63.95 70.8,64.025 62.525,64.15 77.375,64.15 101.65,64.225 10.6,64.6 92.9,64.825 33.35,64.9 59.4,64.95 3.525,65.075 82.075,65.675 57.125,65.75 105.025,66 109.725,66 101.8,66.5 45.025,66.55 37.25,67.075 110.775,67.2 21.05,67.4 88.425,68.125 124.525,68.225 71.025,69.15 94.95,69.15 110.95,69.4 15.125,69.8 102.85,69.85 69.45,70.175 119.825,70.85 16.475,70.975 104.85,71.325 77.3,71.35 88.075,71.55 66.625,71.9 102.425,72.15 6.45,72.375 11.425,72.55 19.25,72.65 124.85,73.375 116.6,73.6 107.6,74.1 78.475,74.25 73.275,74.425 41.925,74.95 86.25,75 34.9,75.1 102.125,75.1 13.8,75.525 1.75,75.95 62.675,76.025 8.95,76.2 68.725,76.225 48.225,76.275 20.7,76.85 26.35,76.85 117.45,77.075 82.075,77.125 28.7,77.225 112.425,77.275 39.375,77.3 84.775,77.45 76.475,77.675 72.9,77.85 21.85,78.35 93.225,78.4 114.325,78.475 34.2,78.6 105.45,78.65 12.575,78.675 33.025,78.75 18.2,79.25 24.275,79.25 8.116,79.309 68.625,79.675 13.05,80.1 20.825,80.45 102.15,80.45 26.5,80.5 96.675,80.5 18.425,80.85 107.925,80.875 24.075,80.975 78.175,81.1 125.275,81.1 111.625,81.15 20.825,81.25 26.5,81.25 66.925,81.375 68.625,81.375 70.325,81.375 92.775,81.4 88.025,81.475 14.1,81.55 18.425,81.575 82.5,81.825 1.45,82.05 98.65,82.1 22.55,82.2 41.65,82.3 85.4,82.375 117.325,82.4 32.626,82.804 37.05,82.925 68.625,83.075 18.5,83.65 24.125,83.85 112.025,83.875 114.025,83.875 116.025,83.875 13.8,84.475 76.75,84.525 64.75,84.725 60,84.8 37.7,84.9 93.95,85.45 57.375,85.475 62.975,85.65 87.925,85.75 36.125,85.825 90.675,85.825 50.327,85.854 112.025,85.875 116.025,85.875 79.025,85.975 20.95,86.025 81.775,86.15 72.95,86.175 85.45,86.175 46.75,86.325 34.375,86.425 44.475,86.525 112.325,87.2 114.125,87.2 115.925,87.2 112.325,88.2 114.125,88.2 115.925,88.2 111.2,88.225 22.7,88.25 77.4,88.3 39.375,88.475 40.85,88.5 110.125,88.525 52.55,88.6 61.275,88.675 104.375,88.75 110.65,88.95 7.9,89 43.65,89.025 71.525,89.075 115.975,89.25 112.075,89.325 114.075,89.325 69,89.475 111.025,89.525 48.55,89.675 28.05,89.775 64.6,89.825 84.25,89.975 86.65,89.975 55.025,90.025 80.325,90.075 89.275,90.075 1.825,90.2 91.8,90.225 72.725,90.25 111.2,90.25 58.775,90.375 70.2,90.525 51.225,90.6 67.675,90.7 111.2,90.95 115.975,91.25 112.075,91.325 114.075,91.325 111.2,91.575 108.225,91.675 107.525,91.95 111.225,92.3 108.35,92.575 113.725,92.575 114.35,92.575 111.85,92.65 112.525,92.8 113.125,92.8 114.925,92.8 115.525,92.8 116.15,92.8 116.775,92.8 108.35,93.225 102,93.85 106,93.85 108.175,93.925 108.2,94.575 108.675,95.075 11.025,95.15 109.175,95.475 115.425,95.6 109.8,95.625 110.4,95.625 111,95.625 111.725,95.625 112.325,95.625 112.925,95.625 113.525,95.625 114.125,95.625 114.725,95.625 116.125,95.625 116.775,95.625 102.3,95.85 106,95.85 108,95.85 39.6,95.925 32.85,95.95 104,95.975
  other v2: 71.895,32.07 63.3,42.05
  other v3: 67.525,33.175 66.975,35.125 33.975,87.35 31.975,87.75 33.975,88.55 31.575,89.35
GNDDetect: R74.2 U12.K13 | length 5.5
  Top Layer w0.1: U12.K13@112.675,46.6 113,46.275 114.25,46.275 115.05,45.475 115.05,44.825 115.5,44.375 R74.2@116.85,44.375
HSE_IN: C98.2 U14.T3 X4.3 | length 6.6
  Top Layer w0.075: 65.175,31.075 65.561,31.075 67.221,32.735 67.396,32.735 68.16,32.735 68.329,32.904 68.729,32.904 U14.T3@68.975,33.15
  Top Layer w0.1: X4.3@63.2,31.075 C98.2@64.375,31.075 65.175,31.075
HSE_OUT: C103.1 U14.U2 X4.1 | length 10.6
  Top Layer w0.075: 65.175,29.875 65.45,30.15 65.45,30.725 67.291,32.566 68.23,32.566 68.309,32.645 68.47,32.645 U14.U2@68.475,32.65
  Top Layer w0.1: X4.1@61.9,30.075 C103.1@61.9,29 61.928,28.972 61.928,28.629 62.256,28.3 64.125,28.3 64.6,28.775 64.6,29.3 65.175,29.875
I2C1_SCL: CN8.28 R11.1 R62.1 U14.A6 U21.26 | length 150.4
  Top Layer w0.075: U14.A6@70.475,40.65 70.475,43.125
  Top Layer w0.1: v1(70.05,44.875) 70.05,43.725 70.475,43.3 70.475,43.125 ; R11.1@71,87.25 71.65,87.25 74.64,90.24 CN8.28@74.64,92.23 ; v2(96.45,47.675) R62.1@96.45,48.25 ; v1(98.325,22.95) U21.26@99.2,22.95
  Signal Layer 2 w0.1: v1(70.05,44.875) 71.4,46.225 72.6,46.225 73.8,47.425 78.217,47.425 79.217,48.425 80.659,48.425 80.734,48.35 95.775,48.35 v2(96.45,47.675) 96.525,47.675 97.05,47.15 97.05,46.75 102.95,40.85 v1(102.95,39.35) ; v1(75.875,72.625) 98.508,72.625 99.658,71.475 v1(102.95,71.475)
  Bottom Layer w0.1: CN8.28@74.64,92.23 75.875,90.995 v1(75.875,72.625) ; v1(98.325,22.95) 102.275,26.9 102.275,30.625 102.95,31.3 v1(102.95,39.35) 102.95,43.2 103.325,43.575 103.325,71.1 v1(102.95,71.475)
I2C1_SDA: CN8.27 R10.1 R63.1 U14.B9 U21.27 | length 158.7
  Top Layer w0.075: U14.B9@71.975,40.15 71.964,40.161 71.964,40.311 71.728,40.547 71.728,41.743 72.2,42.215 72.2,43.125
  Top Layer w0.1: R10.1@69.925,87.25 69.925,87.7 70.175,87.95 71.75,87.95 73.375,89.575 73.375,93.505 CN8.27@74.64,94.77 ; v1(71.575,44.875) 72.2,44.25 72.2,43.125 ; v1(96.575,46.95) 97.525,47.9 R63.1@97.525,48.25 ; v1(97.55,22.8) 97.9,22.45 U21.27@99.2,22.45
  Signal Layer 2 w0.1: v1(71.575,44.875) 73.925,47.225 78.3,47.225 79.3,48.225 80.576,48.225 80.651,48.15 95.367,48.15 96.567,46.95 v1(96.575,46.95) 96.575,46.942 102.375,41.142 v1(102.375,38.975) ; v1(74.65,72.125) 98.725,72.125 99.875,70.975 v1(102.375,70.975)
  Bottom Layer w0.1: v1@74.64,72.125 74.64,90.075 73.375,91.34 73.375,93.505 CN8.27@74.64,94.77 ; v1(97.55,22.8) 97.574,22.8 98.149,23.375 98.225,23.375 102.075,27.225 102.075,30.825 102.375,31.125 v1(102.375,38.975) 102.289,39.061 102.289,39.245 102.275,39.259 102.275,70.753 102.375,70.853 v1(102.375,70.975)
I2C4_SCL: R75.1 U14.A9 U19.4 | length 65.8
  Top Layer w0.075: U14.A9@71.975,40.65 71.975,41.625 72.525,42.175 72.525,43.125
  Top Layer w0.1: U19.4@38.175,26.075 37.85,26.075 36.975,26.95 36.975,28.387 35.575,29.787 35.575,33.975 39.425,37.825 39.425,43.9 v1(39.125,44.2) R75.1@38.4,44.2 ; 72.525,43.125 72.525,43.75 72.85,44.075 v1(72.85,44.8)
  Signal Layer 2 w0.09: 64.811,41.9 65.011,41.7 70.875,41.7 72.3,43.125
  Signal Layer 2 w0.1: v1(39.125,44.2) 39.125,45.401 39.449,45.725 39.979,45.725 40.054,45.65 41.737,45.65 44.437,42.95 54.275,42.95 55.675,41.55 61.175,41.55 61.775,40.95 62.85,40.95 63.8,41.9 64.811,41.9 ; 72.3,43.125 72.85,43.675 v1(72.85,44.8)
I2C4_SDA: R71.1 U14.A15 U19.3 | length 63.9
  Top Layer w0.075: U14.A15@74.975,40.65 74.975,42.4 v1@75.175,42.6
  Top Layer w0.1: U19.3@38.175,26.475 37.85,26.475 37.175,27.15 37.175,28.47 35.775,29.87 35.775,33.825 39.625,37.675 v1(39.625,45.3) R71.1@38.4,45.3
  Signal Layer 2 w0.09: 65.175,41.5 71.163,41.5 72.238,42.575 v1(75.15,42.575)
  Signal Layer 2 w0.1: v1(39.625,45.3) 39.775,45.45 41.654,45.45 44.354,42.75 50.919,42.75 51.89,41.779 53.259,41.779 53.877,42.397 54.503,42.397 55.575,41.325 61.117,41.325 61.717,40.725 62.908,40.725 63.883,41.7 64.575,41.7 64.775,41.5 65.175,41.5
I2C5_SCL_1V8: R169.1 R171.1 TR2.2 U2.F5 | length 24.7
  Signal Layer 1 w0.1: v1(29.675,87) 29.683,87 30.883,88.2 31.898,88.2 31.948,88.15 v3(31.975,88.15)
  Signal Layer 2 w0.1: v1(15.675,89.25) 15.675,87.95 16.65,86.975 23.775,86.975 v1(25.5,88.7) 27.2,87 v1(29.675,87)
  Bottom Layer w0.1: R169.1@14.7,92.15 14.825,92.025 14.825,91.125 TR2.2@15.2,90.75 TR2.2@15.2,90.125 ; v1(15.675,89.25) 15.2,89.725 TR2.2@15.2,90.125 ; R171.1@16.625,90 16.5,90.125 TR2.2@15.2,90.125
I2C5_SDA_1V8: R168.1 R170.1 TR1.2 U2.G6 | length 15.5
  Top Layer w0.1: v2(30.975,87.75) U2.G6@31.575,87.75
  Signal Layer 2 w0.1: v1(22.2,89.425) 22.725,88.9 24.925,88.9 25.15,89.125 26.875,89.125 27.25,88.75 27.25,88.025 27.675,87.6 29.625,87.6 29.775,87.75 v2(30.975,87.75)
  Bottom Layer w0.1: R168.1@19.45,92.15 19.575,92.025 19.575,91.125 TR1.2@19.95,90.75 19.95,90.25 21.15,90.25 21.496,89.904 21.721,89.904 v1(22.2,89.425)
I_SENSE_VDD: C110.2 C111.1 CN14.14 L6.2 R123.1 R124.1 | length 51.4
  Signal Layer 3 w0.2: CN14.14@26.12,4.28 27.19,5.35 28.35,5.35 33.167,10.167 43.583,10.167 44.875,11.459 44.875,13.75 45.475,14.35 46.541,14.35 49.991,17.8 55.866,17.8 58.871,20.805 58.871,25.704 57.375,27.2 54.45,27.2 54.3,27.35 v1(54.3,27.675)
"I_SENSE_VDD CPU": C115.1 C116.2 CN14.2 L7.2 R126.1 R127.1 | length 35.1
  Signal Layer 3 w0.2: CN14.2@10.88,4.28 9.81,5.35 9.259,5.35 8.875,5.734 8.875,7.766 14.259,13.15 17.009,13.15 18.425,14.566 18.425,19.591 25.484,26.65 27.975,26.65 28.2,26.875 v1(28.2,27.175)
I_SENSE_VDD_CORE: C126.2 C127.1 CN14.10 L9.2 R131.1 R132.1 | length 47
  Signal Layer 3 w0.2: CN14.10@21.04,4.28 22.325,5.565 22.325,7.539 23.277,8.492 24.067,8.492 32.325,16.75 37.283,16.75 38.202,17.668 38.202,18.523 38.63,18.951 41.949,18.951 ; 41.949,18.95 48.325,18.95 49.45,20.075 53.75,20.075 55.85,22.175 55.85,23.341 55.316,23.875 54.692,23.875 54.575,23.992 54.575,24.325 v1(54.55,24.35)
I_SENSE_VDD_DDR: C128.1 C129.2 CN14.4 L11.2 R137.1 R138.1 | length 28.1
  Signal Layer 3 w0.2: CN14.4@13.42,4.28 12.15,5.55 12.15,8.466 12.859,9.175 15.875,9.175 17.95,11.25 20.8,14.1 20.8,17.816 25.534,22.55 26.9,22.55 27.075,22.725 v1(27.075,23.075)
I_SENSE_VDD_USB: C100.2 CN14.6 R113.1 U19.39 | length 43.9
  Top Layer w0.2: R113.1@39.45,30.175 R113.1@39.525,30.1 ; v1(39.827,29.726) 39.827,29.798 39.725,29.9 R113.1@39.525,30.1 ; C100.2@40.625,30.1 R113.1@39.525,30.1 ; C100.2@40.65,30.075 40.672,30.075 40.802,29.945 40.802,28.655 40.825,28.631 U19.39@40.825,28.025
  Signal Layer 3 w0.2: CN14.6@15.96,4.28 15.96,4.31 17.275,5.625 17.275,7.875 19.2,9.8 22.841,9.8 31.575,18.534 31.575,21.35 32.25,22.025 32.25,26 36.3,30.05 39.608,30.05 39.725,29.933 39.827,29.831 v1(39.827,29.726)
ISENSE_MEAS: TP53.1 U20.4 U21.14 | length 13.6
  Top Layer w0.1: U21.14@103.075,24.95 103.75,25.625 108.6,25.625 109.95,26.975 112.375,26.975 ; TP53.1@112.375,28.325 112.375,26.975 ; U20.4@113.4,25.325 113.4,25.95 112.375,26.975
LCD_B2: CN16.23 U14.D6 | length 26.4
  Top Layer w0.09: v2@70.025,39.15 U14.D6@70.475,39.15
  Bottom Layer w0.09: v2(69.925,39.15) 69.925,39.231 70.025,39.331 70.025,43.125
  Bottom Layer w0.1: CN16.23@65.525,63.15 CN16.23@65.525,63.1 65.525,61.293 65.45,61.218 65.45,49.225 69.225,45.45 69.225,44.975 70.025,44.175 70.025,43.125
LCD_B3: CN16.24 U14.D11 | length 34.4
  Top Layer w0.09: U14.D11@72.975,39.15 72.988,39.163 73.438,39.163 v2@73.45,39.175
  Top Layer w0.1: v1(73.575,45.6) v1(73.575,54.15)
  Signal Layer 2 w0.219: v1(64.7,54.15) 64.75,54.1 73.525,54.1 v1(73.575,54.15)
  Bottom Layer w0.09: v2(73.525,39.225) 73.525,39.975 74.725,41.175 74.725,43.125
  Bottom Layer w0.1: v1(64.7,54.15) 65.025,54.475 CN16.24@65.025,63.1 ; v1(73.575,45.6) 74.725,44.45 74.725,43.125
LCD_B4: CN16.25 U14.B8 | length 31.2
  Top Layer w0.075: 71.309,43.125 71.39,43.043 71.39,40.27 71.475,40.185 U14.B8@71.475,40.15
  Top Layer w0.1: v1(71.1,53.05) 71.1,50.55 71.525,50.125 71.525,49.45 71.05,48.975 71.05,46.649 71.125,46.574 71.125,43.781 71.3,43.606 71.3,43.324 71.309,43.315 71.309,43.125
  Signal Layer 2 w0.219: v1(63.9,53.05) v1(71.1,53.05)
  Bottom Layer w0.1: v1(63.9,53.05) 63.9,57.25 64.774,58.124 64.774,61.458 64.525,61.707 CN16.25@64.525,63.1
LCD_B5: CN16.26 U14.B6 | length 31.2
  Top Layer w0.075: 70.1,43.125 70.1,43.083 70.228,42.954 70.228,40.548 70.45,40.326 70.45,40.175 U14.B6@70.475,40.15
  Top Layer w0.1: v1(69.875,47.775) 69.325,47.225 69.325,45.875 69.625,45.575 69.625,43.85 70.1,43.375 70.1,43.125
  Signal Layer 2 w0.219: v1(63.1,47.775) v1(69.875,47.775)
  Bottom Layer w0.1: v1(63.1,47.775) 63.1,51.5 63.1,57.378 64.453,58.731 64.453,61.178 64.025,61.606 CN16.26@64.025,63.1
LCD_B6: CN16.27 U14.C1 | length 25.7
  Top Layer w0.075: 65.975,43.125 66.31,42.79 66.31,40.69 67.35,39.65 U14.C1@67.975,39.65
  Top Layer w0.1: v1(63.925,60.75) 63.925,54.15 64.65,53.425 64.65,44.45 65.975,43.125
  Bottom Layer w0.1: CN16.27@63.525,63.1 63.525,61.15 v1(63.925,60.75)
LCD_B7: CN16.28 U14.B11 | length 38.2
  Top Layer w0.075: U14.B11@72.975,40.15 72.975,40.187 72.89,40.272 72.89,41.415 73.325,41.85 73.325,43.125
  Top Layer w0.1: 73.325,43.125 73.325,43.414 73.925,44.014 73.925,44.703 74.775,45.553 74.775,48.924 74.7,48.999 74.7,49.351 74.775,49.426 v1(74.775,53.6)
  Signal Layer 2 w0.219: v1(61.5,53.6) v1(74.775,53.6)
  Bottom Layer w0.1: v1(61.5,53.6) 61.5,54.225 62.8,55.525 62.8,58.03 63.575,58.805 63.575,60.271 63.025,60.821 CN16.28@63.025,63.1
LCD_BL: R57.1 U14.A4 | length 32.4
  Top Layer w0.075: 68.325,43.125 68.325,42.5 69.475,41.35 U14.A4@69.475,40.65
  Top Layer w0.1: 68.325,43.125 68.325,49.924 68.275,49.974 68.275,54.575 v1@68.325,54.625 ; v1(84.975,55.45) R57.1@85.775,55.45
  Signal Layer 2 w0.1: v1(68.253,54.628) 73.622,54.628 73.625,54.625 74.025,55.025 84.55,55.025 v1(84.975,55.45)
LCD_BL_A: C54.2 CN16.2 R60.2 | length 17.8
  Top Layer w0.3: v1(82.3,53.1) 83.25,53.1 83.475,53.325 C54.2@83.475,53.9 R60.2@84.5,53.9
  Bottom Layer w0.3: CN16.2@76.025,63.1 76.025,59.475 77.206,58.294 80.9,58.294 82.175,57.019 82.175,55.6 81.95,55.375 81.95,53.518 82.3,53.168 v1(82.3,53.1)
LCD_BL_K: CN16.1 R49.2 U9.4 | length 17.1
  Top Layer w0.3: v1(83.1,55.475) 83.1,57.375 R49.2@82.95,57.525 82.95,57.65 83.575,58.275 U9.4@85.075,58.275
  Bottom Layer w0.3: CN16.1@76.525,63.1 76.525,59.878 77.515,58.888 81.137,58.888 83.1,56.925 v1(83.1,55.475)
LCD_CLK: CN16.30 TP41.1 U14.C9 | length 41.2
  Top Layer w0.075: 71.559,43.125 71.559,40.441 71.725,40.275 71.725,39.9 U14.C9@71.975,39.65
  Top Layer w0.1: TP41.1@62.975,66.125 63.15,65.95 v1(63.15,65.1) ; 71.559,43.125 71.559,43.131 71.521,43.169 71.521,43.971 v1(71.565,44.015)
  Signal Layer 2 w0.219: v1(59.9,44.015) 60.81,44.925 66.751,44.925 67.651,44.025 71.555,44.025 v1(71.565,44.015)
  Bottom Layer w0.1: v1(59.9,44.015) 59.9,51.5 61.025,52.625 61.025,58.734 62.69,60.399 62.69,61.602 62.025,62.267 CN16.30@62.025,63.1 62.025,64.275 62.799,65.049 63.099,65.049 v1(63.15,65.1)
LCD_DE: CN16.34 TP40.1 U14.C12 | length 50.8
  Top Layer w0.075: U14.C12@73.475,39.65 73.221,39.904 73.221,40.279 73.059,40.441 73.059,41.334 73.525,41.8 73.525,43.125
  Top Layer w0.1: TP40.1@58.45,66.025 59.3,66.025 v1(59.65,65.675) ; 73.525,43.125 73.525,43.331 74.125,43.931 74.125,44.621 75.125,45.621 v1(75.125,49.175)
  Signal Layer 2 w0.1: v1(56.7,49.175) 56.822,49.175 56.922,49.075 74.841,49.075 74.855,49.089 75.039,49.089 v1(75.125,49.175)
  Bottom Layer w0.1: v1(56.7,49.175) 56.7,55.6 61.9,60.8 61.9,61.275 61.45,61.725 60.45,61.725 60.025,62.15 CN16.34@60.025,63.1 60.106,63.181 60.106,63.681 60.325,63.9 60.325,65 v1(59.65,65.675)
LCD_DISP: CN16.31 R59.2 U14.AA20 | length 102.1
  Top Layer w0.09: v1(61.325,64.25) R59.2@61.325,64.875 ; U14.AA20@77.474,30.65 77.475,29.27 79.02,27.725
  Top Layer w0.1: 79.02,27.725 81.595,25.15 92.817,25.15 v1(95.075,27.408)
  Signal Layer 2 w0.1: v1(59.1,52.9) 61.475,50.525 68.474,50.525 68.524,50.575 97.2,50.575 v1(97.25,50.525)
  Bottom Layer w0.09: v1(59.1,52.9) 59.492,52.9 60.7,54.108 60.7,58.7 62.495,60.495 62.495,61.522 61.525,62.492 61.525,63.967 61.325,64.167 v1(61.325,64.25)
  Bottom Layer w0.1: v1(95.075,27.408) 96.558,27.408 100.025,30.875 100.025,41.5 97.25,44.275 v1(97.25,50.525)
